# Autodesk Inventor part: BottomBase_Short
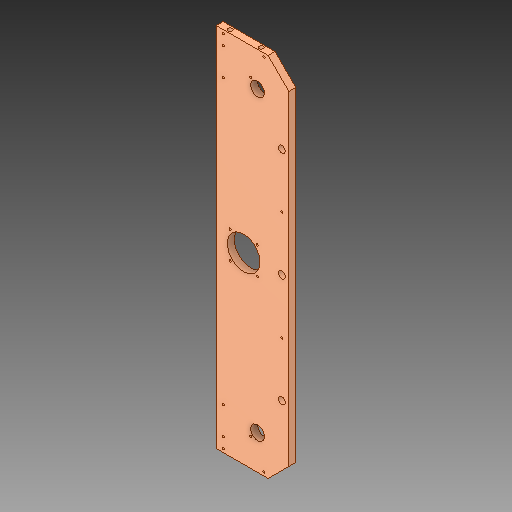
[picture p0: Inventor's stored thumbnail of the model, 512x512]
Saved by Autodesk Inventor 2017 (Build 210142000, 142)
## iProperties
Created: 2017-05
Part Number: BottomBase_Short
Material: Generic
Document SubType Name: Modeling
Designer: Savy
Density: 1 g/cm^3
Appearance: Default
Author: Savy
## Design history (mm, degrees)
feature "SOLID1"
body "Solid1"
